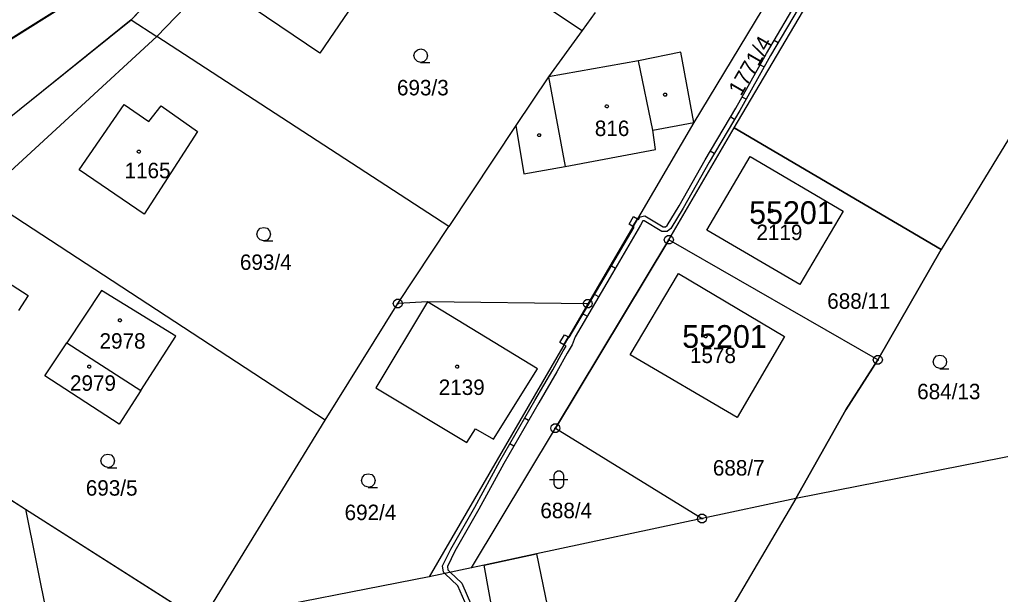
# Model space of a CAD drawing. Extents: x -777309 to -774195, y -1144706 to -1143600.
# Drawn here: x -774798.5 to -774690.7, y -1144632.5 to -1144569.3 of the extents above; entities that cross this region are included whole.
import ezdxf

# ---------------------------------------------------------------- set-up
doc = ezdxf.new("R2010")
doc.units = 0
for name, color, linetype in [('1', 7, 'Continuous'), ('11', 7, 'Continuous'), ('12', 7, 'Continuous'), ('13', 7, 'Continuous'), ('2', 7, 'Continuous'), ('3', 7, 'Continuous'), ('4', 7, 'Continuous'), ('5', 7, 'Continuous'), ('8', 7, 'Continuous')]:
    doc.layers.add(name, color=color, linetype=linetype)

msp = doc.modelspace()

# ---------------------------------------------------------------- linework, layer by layer
at = {"layer": '1'}
for p, q in [((-774719.91, -1144581.17), (-774699.03, -1144545.63)), ((-774786.26, -1144569.27), (-774767.69, -1144549.86)), ((-774783.41, -1144571.12), (-774764.86, -1144551.73)), ((-774764.86, -1144551.73), (-774736.65, -1144570.44)), ((-774759.93, -1144564.77), (-774765.49, -1144572.96)), ((-774714.76, -1144564.69), (-774724.37, -1144580.58)), ((-774791.49, -1144566.35), (-774820.24, -1144584.41)), ((-774765.49, -1144572.96), (-774772.84, -1144567.99)), ((-774806.89, -1144585.87), (-774786.26, -1144569.27)), ((-774735.23, -1144568.48), (-774736.65, -1144570.44)), ((-774783.41, -1144571.12), (-774802.54, -1144588.71)), ((-774751.3, -1144592.01), (-774783.41, -1144571.12)), ((-774736.65, -1144570.44), (-774740.36, -1144575.55)), ((-774740.36, -1144575.55), (-774743.95, -1144580.92)), ((-774791.95, -1144585.79), (-774787.02, -1144578.61)), ((-774787.02, -1144578.61), (-774784.3, -1144580.47)), ((-774784.3, -1144580.47), (-774782.96, -1144578.75)), ((-774782.96, -1144578.75), (-774778.94, -1144581.56)), ((-774743.95, -1144580.92), (-774751.3, -1144592.01)), ((-774724.37, -1144580.58), (-774736.03, -1144600.5)), ((-774727.11, -1144593.47), (-774719.91, -1144581.17)), ((-774697.15, -1144594.52), (-774719.91, -1144581.17)), ((-774688.42, -1144580.24), (-774697.15, -1144594.52)), ((-774778.94, -1144581.56), (-774784.82, -1144590.65)), ((-774722.94, -1144592.4), (-774718.18, -1144584.31)), ((-774718.18, -1144584.31), (-774707.94, -1144590.31)), ((-774784.82, -1144590.65), (-774791.95, -1144585.79)), ((-774764.91, -1144613.3), (-774802.54, -1144588.71)), ((-774707.94, -1144590.31), (-774712.72, -1144598.38)), ((-774756.92, -1144600.48), (-774751.3, -1144592.01)), ((-774712.72, -1144598.38), (-774722.94, -1144592.4)), ((-774727.11, -1144593.47), (-774739.59, -1144614.19)), ((-774704.12, -1144606.68), (-774727.11, -1144593.47)), ((-774704.12, -1144606.68), (-774697.15, -1144594.52)), ((-774731.36, -1144606.11), (-774726.04, -1144597.17)), ((-774726.04, -1144597.17), (-774714.38, -1144604.11)), ((-774789.49, -1144599.05), (-774793.3, -1144604.79)), ((-774781.32, -1144604.06), (-774789.49, -1144599.05)), ((-774764.91, -1144613.3), (-774756.92, -1144600.48)), ((-774753.64, -1144600.28), (-774759.32, -1144609.74)), ((-774753.64, -1144600.28), (-774756.92, -1144600.48)), ((-774736.03, -1144600.5), (-774753.64, -1144600.28)), ((-774741.57, -1144607.66), (-774753.64, -1144600.28)), ((-774736.03, -1144600.5), (-774753.47, -1144630.52)), ((-774795.73, -1144608.42), (-774793.3, -1144604.79)), ((-774793.3, -1144604.79), (-774785.17, -1144610.03)), ((-774785.17, -1144610.03), (-774781.32, -1144604.06)), ((-774714.38, -1144604.11), (-774719.6, -1144612.99)), ((-774719.6, -1144612.99), (-774731.36, -1144606.11)), ((-774707.66, -1144612.15), (-774704.12, -1144606.68)), ((-774822.59, -1144607.36), (-774797.88, -1144623.07)), ((-774746.39, -1144615.4), (-774741.57, -1144607.66)), ((-774787.58, -1144613.73), (-774795.73, -1144608.42)), ((-774785.17, -1144610.03), (-774787.58, -1144613.73)), ((-774759.32, -1144609.74), (-774749.33, -1144615.74)), ((-774713.16, -1144621.91), (-774707.66, -1144612.15)), ((-774778.49, -1144635.4), (-774764.91, -1144613.3)), ((-774749.33, -1144615.74), (-774748.37, -1144614.25)), ((-774748.83, -1144629.53), (-774739.59, -1144614.19)), ((-774748.37, -1144614.25), (-774746.39, -1144615.4)), ((-774739.59, -1144614.19), (-774723.46, -1144624.12)), ((-774671.75, -1144613.78), (-774713.16, -1144621.91)), ((-774713.16, -1144621.91), (-774723.46, -1144624.12)), ((-774713.16, -1144621.91), (-774722.81, -1144638.31)), ((-774797.88, -1144623.07), (-774794.67, -1144638.8)), ((-774797.88, -1144623.07), (-774778.49, -1144635.4)), ((-774723.46, -1144624.12), (-774741.65, -1144628)), ((-774747.42, -1144629.23), (-774741.65, -1144628)), ((-774748.83, -1144629.53), (-774753.47, -1144630.52)), ((-774747.42, -1144629.23), (-774748.83, -1144629.53)), ((-774753.47, -1144630.52), (-774778.49, -1144635.4))]:
    msp.add_line(p, q, dxfattribs=at)
msp.add_lwpolyline([(-774803.94, -1144597.81), (-774802.87, -1144596.17), (-774797.57, -1144599.61), (-774798.65, -1144601.26)], dxfattribs=at)
at = {"layer": '11'}
for points in [[(-774820.24, -1144584.41), (-774788.6, -1144564.54), (-774782.2, -1144557.11), (-774781.07, -1144557.53), (-774762.07, -1144538.45), (-774762.57, -1144536.62), (-774756.52, -1144531.36), (-774752.52, -1144526.08), (-774747.9, -1144520.81), (-774739.5, -1144510.72), (-774739.53, -1144511.98), (-774736.01, -1144514.94), (-774748.16, -1144529.45), (-774767.69, -1144549.86), (-774786.26, -1144569.27), (-774806.89, -1144585.87)], [(-774822.59, -1144607.36), (-774797.88, -1144623.07), (-774778.49, -1144635.4), (-774794.67, -1144638.8), (-774813.19, -1144642.7)]]:
    msp.add_lwpolyline(points, dxfattribs=at)
for points in [[(-774748.83, -1144629.53), (-774739.59, -1144614.19), (-774727.11, -1144593.47), (-774719.91, -1144581.17), (-774697.15, -1144594.52), (-774704.12, -1144606.68), (-774707.66, -1144612.15), (-774713.16, -1144621.91), (-774723.46, -1144624.12), (-774741.65, -1144628), (-774747.42, -1144629.23)], [(-774718.18, -1144584.31), (-774707.94, -1144590.31), (-774712.72, -1144598.38), (-774722.94, -1144592.4)], [(-774726.04, -1144597.17), (-774714.38, -1144604.11), (-774719.6, -1144612.99), (-774731.36, -1144606.11)]]:
    msp.add_lwpolyline(points, close=True, dxfattribs=at)
at = {"layer": '12'}
for p, q in [((-774759.93, -1144564.77), (-774765.49, -1144572.96)), ((-774765.49, -1144572.96), (-774772.84, -1144567.99)), ((-774730.44, -1144573.78), (-774740.36, -1144575.55)), ((-774728.86, -1144581.43), (-774730.44, -1144573.78)), ((-774740.36, -1144575.55), (-774738.53, -1144585.42)), ((-774791.95, -1144585.79), (-774787.02, -1144578.61)), ((-774787.02, -1144578.61), (-774784.3, -1144580.47)), ((-774784.3, -1144580.47), (-774782.96, -1144578.75)), ((-774782.96, -1144578.75), (-774778.94, -1144581.56)), ((-774778.94, -1144581.56), (-774784.82, -1144590.65)), ((-774728.57, -1144583.53), (-774728.86, -1144581.43)), ((-774738.53, -1144585.42), (-774728.57, -1144583.53)), ((-774722.94, -1144592.4), (-774718.18, -1144584.31)), ((-774718.18, -1144584.31), (-774707.94, -1144590.31)), ((-774784.82, -1144590.65), (-774791.95, -1144585.79)), ((-774707.94, -1144590.31), (-774712.72, -1144598.38)), ((-774712.72, -1144598.38), (-774722.94, -1144592.4)), ((-774731.36, -1144606.11), (-774726.04, -1144597.17)), ((-774726.04, -1144597.17), (-774714.38, -1144604.11)), ((-774789.49, -1144599.05), (-774793.3, -1144604.79)), ((-774781.32, -1144604.06), (-774789.49, -1144599.05)), ((-774753.64, -1144600.28), (-774759.32, -1144609.74)), ((-774741.57, -1144607.66), (-774753.64, -1144600.28)), ((-774795.73, -1144608.42), (-774793.3, -1144604.79)), ((-774793.3, -1144604.79), (-774785.17, -1144610.03)), ((-774793.3, -1144604.79), (-774785.17, -1144610.03)), ((-774785.17, -1144610.03), (-774781.32, -1144604.06)), ((-774714.38, -1144604.11), (-774719.6, -1144612.99)), ((-774719.6, -1144612.99), (-774731.36, -1144606.11)), ((-774746.39, -1144615.4), (-774741.57, -1144607.66)), ((-774787.58, -1144613.73), (-774795.73, -1144608.42)), ((-774785.17, -1144610.03), (-774787.58, -1144613.73)), ((-774759.32, -1144609.74), (-774749.33, -1144615.74)), ((-774749.33, -1144615.74), (-774748.37, -1144614.25)), ((-774748.37, -1144614.25), (-774746.39, -1144615.4))]:
    msp.add_line(p, q, dxfattribs=at)
at = {"layer": '13'}
for p, q in [((-774716.36, -1144572.98), (-774712.74, -1144566.8)), ((-774712.3, -1144567.06), (-774715.92, -1144573.22)), ((-774715.09, -1144571.8), (-774715.52, -1144571.55)), ((-774719.75, -1144579.01), (-774716.36, -1144572.98)), ((-774715.92, -1144573.22), (-774719.31, -1144579.27)), ((-774717.05, -1144574.22), (-774716.62, -1144574.46)), ((-774718.61, -1144578.02), (-774719.04, -1144577.77)), ((-774723.13, -1144584.68), (-774719.75, -1144579.01)), ((-774719.31, -1144579.27), (-774722.69, -1144584.94)), ((-774720.31, -1144579.96), (-774719.88, -1144580.21)), ((-774722.13, -1144583.99), (-774722.56, -1144583.74)), ((-774725.99, -1144589.74), (-774723.13, -1144584.68)), ((-774722.69, -1144584.94), (-774725.55, -1144590)), ((-774727.28, -1144591.88), (-774725.99, -1144589.74)), ((-774730.28, -1144590.96), (-774729.74, -1144590.83)), ((-774729.74, -1144590.83), (-774727.74, -1144592.05)), ((-774725.55, -1144590), (-774726.9, -1144592.22)), ((-774730.24, -1144591.87), (-774733.29, -1144597.15)), ((-774731.06, -1144592.01), (-774730.56, -1144591.15)), ((-774730.56, -1144591.15), (-774730.44, -1144591.22)), ((-774730.44, -1144591.22), (-774730.28, -1144590.96)), ((-774729.96, -1144591.4), (-774730.24, -1144591.87)), ((-774729.82, -1144591.37), (-774729.96, -1144591.4)), ((-774727.88, -1144592.55), (-774729.82, -1144591.37)), ((-774727.48, -1144592.04), (-774727.28, -1144591.88)), ((-774733.73, -1144596.89), (-774730.94, -1144592.08)), ((-774730.94, -1144592.08), (-774731.06, -1144592.01)), ((-774727.3, -1144592.54), (-774727.88, -1144592.55)), ((-774727.74, -1144592.05), (-774727.48, -1144592.04)), ((-774726.9, -1144592.22), (-774727.3, -1144592.54)), ((-774738.06, -1144604.2), (-774733.73, -1144596.89)), ((-774733.29, -1144597.15), (-774737.43, -1144604.13)), ((-774732.99, -1144596.63), (-774733.42, -1144596.38)), ((-774735.26, -1144599.47), (-774734.83, -1144599.72)), ((-774736.1, -1144601.88), (-774736.53, -1144601.63)), ((-774738.65, -1144605.02), (-774738.15, -1144604.15)), ((-774738.15, -1144604.15), (-774738.06, -1144604.2)), ((-774737.43, -1144604.13), (-774737.75, -1144605.02)), ((-774739.87, -1144607.76), (-774738.72, -1144605.68)), ((-774738.28, -1144605.92), (-774739.43, -1144608)), ((-774738.72, -1144605.68), (-774738.41, -1144605.16)), ((-774738.41, -1144605.16), (-774738.65, -1144605.02)), ((-774737.75, -1144605.02), (-774738.28, -1144605.92)), ((-774741.86, -1144611.12), (-774739.87, -1144607.76)), ((-774739.43, -1144608), (-774741.42, -1144611.38)), ((-774745.7, -1144617.82), (-774741.86, -1144611.12)), ((-774741.42, -1144611.38), (-774745.26, -1144618.06)), ((-774742.97, -1144613.05), (-774742.53, -1144613.3)), ((-774744.16, -1144616.15), (-774744.59, -1144615.9)), ((-774748.46, -1144622.85), (-774745.7, -1144617.82)), ((-774745.26, -1144618.06), (-774748.02, -1144623.09)), ((-774751.08, -1144627.47), (-774748.46, -1144622.85)), ((-774748.02, -1144623.09), (-774750.64, -1144627.71)), ((-774751.99, -1144629.31), (-774751.08, -1144627.47)), ((-774750.64, -1144627.71), (-774751.47, -1144629.39)), ((-774751.91, -1144630), (-774751.99, -1144629.31)), ((-774751.47, -1144629.39), (-774751.43, -1144629.76)), ((-774751.75, -1144630.15), (-774751.91, -1144630)), ((-774750.3, -1144631.53), (-774751.75, -1144630.15)), ((-774751.43, -1144629.76), (-774751.15, -1144630.03)), ((-774751.15, -1144630.03), (-774749.88, -1144631.23)), ((-774749.29, -1144633.85), (-774750.3, -1144631.53)), ((-774749.88, -1144631.23), (-774748.81, -1144633.69))]:
    msp.add_line(p, q, dxfattribs=at)
for points in [[(-774731.06, -1144592.01), (-774731.49, -1144591.76), (-774730.99, -1144590.89), (-774730.56, -1144591.15)], [(-774738.58, -1144603.9), (-774738.15, -1144604.15), (-774738.65, -1144605.02), (-774739.09, -1144604.76)]]:
    msp.add_lwpolyline(points, close=True, dxfattribs=at)
at = {"layer": '3'}
for points in [[(-774754.39, -1144573.96), (-774754.77, -1144573.86), (-774755.04, -1144573.59), (-774755.14, -1144573.22), (-774755.04, -1144572.85), (-774754.77, -1144572.58), (-774754.4, -1144572.48), (-774754.03, -1144572.58), (-774753.76, -1144572.85), (-774753.66, -1144573.23), (-774753.76, -1144573.61), (-774754.03, -1144573.88), (-774754.41, -1144573.98), (-774753.41, -1144573.98)], [(-774771.66, -1144593.58), (-774772.04, -1144593.48), (-774772.31, -1144593.21), (-774772.41, -1144592.84), (-774772.31, -1144592.47), (-774772.04, -1144592.2), (-774771.67, -1144592.1), (-774771.3, -1144592.2), (-774771.03, -1144592.47), (-774770.93, -1144592.85), (-774771.03, -1144593.23), (-774771.3, -1144593.5), (-774771.68, -1144593.6), (-774770.68, -1144593.6)], [(-774697.29, -1144607.62), (-774697.67, -1144607.52), (-774697.94, -1144607.25), (-774698.04, -1144606.88), (-774697.94, -1144606.51), (-774697.67, -1144606.24), (-774697.3, -1144606.14), (-774696.93, -1144606.24), (-774696.66, -1144606.51), (-774696.56, -1144606.89), (-774696.66, -1144607.27), (-774696.93, -1144607.54), (-774697.31, -1144607.64), (-774696.31, -1144607.64)], [(-774788.81, -1144618.51), (-774789.19, -1144618.41), (-774789.46, -1144618.14), (-774789.56, -1144617.77), (-774789.46, -1144617.4), (-774789.19, -1144617.13), (-774788.82, -1144617.03), (-774788.45, -1144617.13), (-774788.18, -1144617.4), (-774788.08, -1144617.78), (-774788.18, -1144618.16), (-774788.45, -1144618.43), (-774788.83, -1144618.53), (-774787.83, -1144618.53)], [(-774760.15, -1144620.67), (-774760.53, -1144620.57), (-774760.8, -1144620.3), (-774760.9, -1144619.93), (-774760.8, -1144619.56), (-774760.53, -1144619.29), (-774760.16, -1144619.19), (-774759.79, -1144619.29), (-774759.52, -1144619.56), (-774759.42, -1144619.94), (-774759.52, -1144620.32), (-774759.79, -1144620.59), (-774760.17, -1144620.69), (-774759.17, -1144620.69)], [(-774740.22, -1144619.83), (-774738.95, -1144619.83), (-774738.22, -1144619.83)]]:
    msp.add_lwpolyline(points, dxfattribs=at)
msp.add_lwpolyline([(-774739.72, -1144619.33), (-774739.62, -1144619.04), (-774739.37, -1144618.86), (-774739.06, -1144618.86), (-774738.81, -1144619.04), (-774738.71, -1144619.33), (-774738.71, -1144620.33), (-774738.81, -1144620.62), (-774739.06, -1144620.8), (-774739.37, -1144620.8), (-774739.62, -1144620.62), (-774739.72, -1144620.33)], close=True, dxfattribs=at)
at = {"layer": '4'}
for p, q in [((-774786.26, -1144569.27), (-774783.41, -1144571.12)), ((-774725.8, -1144572.84), (-774730.44, -1144573.78)), ((-774724.37, -1144580.58), (-774725.8, -1144572.84)), ((-774730.44, -1144573.78), (-774740.36, -1144575.55)), ((-774728.86, -1144581.43), (-774730.44, -1144573.78)), ((-774740.36, -1144575.55), (-774738.53, -1144585.42)), ((-774743.95, -1144580.92), (-774743.06, -1144586.23)), ((-774728.86, -1144581.43), (-774724.37, -1144580.58)), ((-774728.57, -1144583.53), (-774728.86, -1144581.43)), ((-774738.53, -1144585.42), (-774728.57, -1144583.53)), ((-774743.06, -1144586.23), (-774738.53, -1144585.42)), ((-774741.65, -1144628), (-774735.16, -1144659.31)), ((-774740.35, -1144668.12), (-774747.42, -1144629.23))]:
    msp.add_line(p, q, dxfattribs=at)
at = {"layer": '5'}
for points in [[(-774727.43, -1144577.36), (-774727.34, -1144577.51), (-774727.43, -1144577.66), (-774727.61, -1144577.66), (-774727.7, -1144577.51), (-774727.61, -1144577.36)], [(-774733.93, -1144578.63), (-774733.83, -1144578.65), (-774733.78, -1144578.74), (-774733.76, -1144578.8), (-774733.78, -1144578.89), (-774733.86, -1144578.96), (-774733.93, -1144578.97), (-774734.02, -1144578.94), (-774734.08, -1144578.88), (-774734.1, -1144578.8), (-774734.08, -1144578.71), (-774734, -1144578.64)], [(-774741.29, -1144581.8), (-774741.2, -1144581.95), (-774741.29, -1144582.1), (-774741.47, -1144582.1), (-774741.56, -1144581.95), (-774741.47, -1144581.8)], [(-774785.4, -1144583.61), (-774785.3, -1144583.63), (-774785.25, -1144583.72), (-774785.23, -1144583.78), (-774785.25, -1144583.87), (-774785.33, -1144583.94), (-774785.4, -1144583.95), (-774785.49, -1144583.92), (-774785.55, -1144583.86), (-774785.57, -1144583.78), (-774785.55, -1144583.69), (-774785.47, -1144583.62)], [(-774715.77, -1144590.11), (-774715.67, -1144590.13), (-774715.62, -1144590.22), (-774715.6, -1144590.28), (-774715.62, -1144590.37), (-774715.7, -1144590.44), (-774715.77, -1144590.45), (-774715.86, -1144590.42), (-774715.92, -1144590.36), (-774715.94, -1144590.28), (-774715.92, -1144590.19), (-774715.84, -1144590.12)], [(-774787.48, -1144602.15), (-774787.38, -1144602.17), (-774787.33, -1144602.26), (-774787.31, -1144602.32), (-774787.33, -1144602.41), (-774787.41, -1144602.48), (-774787.48, -1144602.49), (-774787.57, -1144602.46), (-774787.63, -1144602.4), (-774787.65, -1144602.32), (-774787.63, -1144602.23), (-774787.55, -1144602.16)], [(-774723.08, -1144603.9), (-774722.98, -1144603.92), (-774722.93, -1144604.01), (-774722.91, -1144604.07), (-774722.93, -1144604.16), (-774723.01, -1144604.23), (-774723.08, -1144604.24), (-774723.17, -1144604.21), (-774723.23, -1144604.15), (-774723.25, -1144604.07), (-774723.23, -1144603.98), (-774723.15, -1144603.91)], [(-774790.85, -1144607.25), (-774790.75, -1144607.27), (-774790.7, -1144607.36), (-774790.68, -1144607.42), (-774790.7, -1144607.51), (-774790.78, -1144607.58), (-774790.85, -1144607.59), (-774790.94, -1144607.56), (-774791, -1144607.5), (-774791.02, -1144607.42), (-774791, -1144607.33), (-774790.92, -1144607.26)], [(-774750.4, -1144607.24), (-774750.3, -1144607.26), (-774750.25, -1144607.35), (-774750.23, -1144607.41), (-774750.25, -1144607.5), (-774750.33, -1144607.57), (-774750.4, -1144607.58), (-774750.49, -1144607.55), (-774750.55, -1144607.49), (-774750.57, -1144607.41), (-774750.55, -1144607.32), (-774750.47, -1144607.25)]]:
    msp.add_lwpolyline(points, close=True, dxfattribs=at)
at = {"layer": '8'}
for p, q in [((-774727.23, -1144593.47), (-774726.99, -1144593.47)), ((-774757.04, -1144600.48), (-774756.8, -1144600.48)), ((-774736.15, -1144600.5), (-774735.91, -1144600.5)), ((-774704.24, -1144606.68), (-774704, -1144606.68)), ((-774739.71, -1144614.19), (-774739.47, -1144614.19)), ((-774723.58, -1144624.12), (-774723.34, -1144624.12))]:
    msp.add_line(p, q, dxfattribs=at)
for points in [[(-774726.96, -1144592.99), (-774726.71, -1144593.17), (-774726.61, -1144593.46), (-774726.71, -1144593.75), (-774726.96, -1144593.93), (-774727.27, -1144593.93), (-774727.52, -1144593.75), (-774727.62, -1144593.46), (-774727.52, -1144593.17), (-774727.27, -1144592.99)], [(-774756.77, -1144600), (-774756.52, -1144600.18), (-774756.42, -1144600.47), (-774756.52, -1144600.76), (-774756.77, -1144600.94), (-774757.08, -1144600.94), (-774757.33, -1144600.76), (-774757.43, -1144600.47), (-774757.33, -1144600.18), (-774757.08, -1144600)], [(-774735.88, -1144600.02), (-774735.63, -1144600.2), (-774735.53, -1144600.49), (-774735.63, -1144600.78), (-774735.88, -1144600.96), (-774736.19, -1144600.96), (-774736.44, -1144600.78), (-774736.54, -1144600.49), (-774736.44, -1144600.2), (-774736.19, -1144600.02)], [(-774703.97, -1144606.2), (-774703.72, -1144606.38), (-774703.62, -1144606.67), (-774703.72, -1144606.96), (-774703.97, -1144607.14), (-774704.28, -1144607.14), (-774704.53, -1144606.96), (-774704.63, -1144606.67), (-774704.53, -1144606.38), (-774704.28, -1144606.2)], [(-774739.44, -1144613.71), (-774739.19, -1144613.89), (-774739.09, -1144614.18), (-774739.19, -1144614.47), (-774739.44, -1144614.65), (-774739.75, -1144614.65), (-774740, -1144614.47), (-774740.1, -1144614.18), (-774740, -1144613.89), (-774739.75, -1144613.71)], [(-774723.31, -1144623.64), (-774723.06, -1144623.82), (-774722.96, -1144624.11), (-774723.06, -1144624.4), (-774723.31, -1144624.58), (-774723.62, -1144624.58), (-774723.87, -1144624.4), (-774723.97, -1144624.11), (-774723.87, -1144623.82), (-774723.62, -1144623.64)]]:
    msp.add_lwpolyline(points, close=True, dxfattribs=at)

# ---------------------------------------------------------------- texts
at = {"layer": '11'}
for p in [(-774718.28, -1144591.73), (-774725.64, -1144605.35)]:
    msp.add_text('55201', height=2.5, dxfattribs=at).set_placement(p)
at = {"layer": '2'}
msp.add_text('1771/4', height=1.7, rotation=59.9887, dxfattribs=at).set_placement((-774719.18, -1144577.75))
for s, p in [('693/3', (-774757.01, -1144577.59)), ('816', (-774735.25, -1144582.06)), ('1165', (-774786.97, -1144586.7)), ('2119', (-774717.48, -1144593.5)), ('693/4', (-774774.28, -1144596.78)), ('688/11', (-774709.69, -1144601.05)), ('2978', (-774789.72, -1144605.44)), ('1578', (-774724.79, -1144607.02)), ('2979', (-774792.97, -1144610.07)), ('2139', (-774752.42, -1144610.53)), ('684/13', (-774699.8, -1144611)), ('688/7', (-774722.27, -1144619.39)), ('693/5', (-774791.23, -1144621.6)), ('692/4', (-774762.77, -1144624.29)), ('688/4', (-774741.24, -1144624.08))]:
    msp.add_text(s, height=1.7, dxfattribs=at).set_placement(p)

doc.saveas('drawing.dxf')
